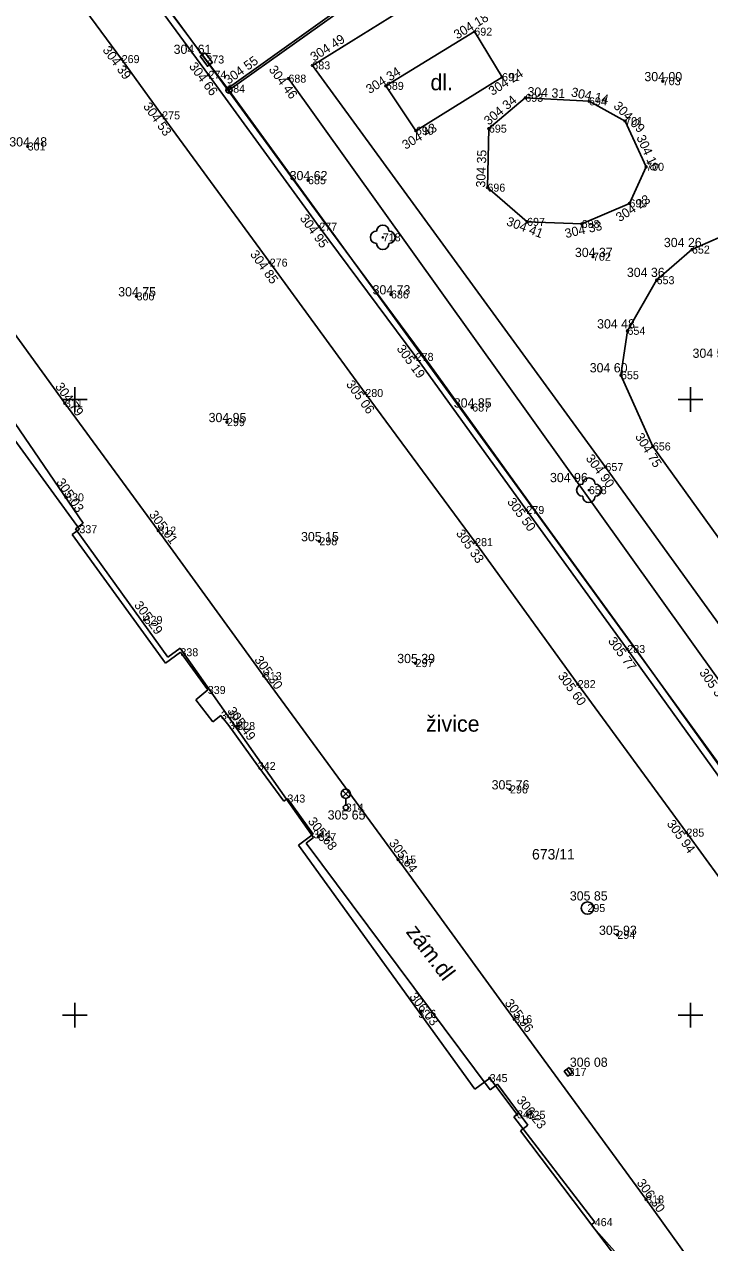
# Model space of a CAD drawing. Extents: x -492811 to -492366, y -1127107 to -1126748.
# Drawn here: x -492641.63 to -492619.38, y -1126927.39 to -1126887.82 of the extents above; entities that cross this region are included whole.
import ezdxf

# ---------------------------------------------------------------- set-up
doc = ezdxf.new("R2010")
doc.units = 0
for name, color, linetype in [('body', 7, 'Continuous'), ('kanalizace', 7, 'Continuous'), ('katastrální mapa', 7, 'Continuous'), ('oplocení', 7, 'Continuous'), ('plyn', 7, 'Continuous'), ('podrobný výškový bod', 7, 'Continuous'), ('popis ploch', 7, 'Continuous'), ('rozhraní ploch', 7, 'Continuous'), ('stavební objekt', 7, 'Continuous'), ('stromy', 7, 'Continuous'), ('síť', 7, 'Continuous'), ('veřejné osvětlení', 7, 'Continuous'), ('vstup na pozemek', 7, 'Continuous'), ('výšky', 7, 'Continuous'), ('čísla bodů', 7, 'Continuous')]:
    doc.layers.add(name, color=color, linetype=linetype)

msp = doc.modelspace()

# ---------------------------------------------------------------- linework, layer by layer
at = {"layer": 'body'}
for p, q in [((-492627.022, -1126888.052), (-492627.022, -1126888.052)), ((-492638.475, -1126888.943), (-492638.475, -1126888.943)), ((-492635.726, -1126888.956), (-492635.726, -1126888.956)), ((-492635.656, -1126889.453), (-492635.656, -1126889.453)), ((-492632.283, -1126889.147), (-492632.283, -1126889.147)), ((-492635.048, -1126889.905), (-492635.048, -1126889.905)), ((-492633.06, -1126889.577), (-492633.06, -1126889.577)), ((-492629.894, -1126889.813), (-492629.894, -1126889.813)), ((-492626.122, -1126889.528), (-492626.122, -1126889.528)), ((-492620.903, -1126889.662), (-492620.903, -1126889.662)), ((-492625.366, -1126890.2), (-492625.366, -1126890.2)), ((-492623.298, -1126890.315), (-492623.298, -1126890.315)), ((-492637.159, -1126890.77), (-492637.159, -1126890.77)), ((-492622.123, -1126890.955), (-492622.123, -1126890.955)), ((-492628.919, -1126891.27), (-492628.919, -1126891.27)), ((-492626.549, -1126891.202), (-492626.549, -1126891.202)), ((-492641.528, -1126891.781), (-492641.528, -1126891.781)), ((-492621.442, -1126892.441), (-492621.442, -1126892.441)), ((-492632.423, -1126892.877), (-492632.423, -1126892.877)), ((-492626.597, -1126893.119), (-492626.597, -1126893.119)), ((-492621.986, -1126893.629), (-492621.986, -1126893.629)), ((-492625.309, -1126894.23), (-492625.309, -1126894.23)), ((-492632.058, -1126894.387), (-492632.058, -1126894.387)), ((-492623.536, -1126894.298), (-492623.536, -1126894.298)), ((-492629.995, -1126894.732), (-492629.995, -1126894.732)), ((-492623.168, -1126895.362), (-492623.168, -1126895.362)), ((-492619.955, -1126895.131), (-492619.955, -1126895.131)), ((-492633.667, -1126895.554), (-492633.667, -1126895.554)), ((-492621.102, -1126896.125), (-492621.102, -1126896.125)), ((-492629.73, -1126896.587), (-492629.73, -1126896.587)), ((-492637.991, -1126896.651), (-492637.991, -1126896.651)), ((-492622.049, -1126897.769), (-492622.049, -1126897.769)), ((-492628.927, -1126898.616), (-492628.927, -1126898.616)), ((-492622.26, -1126899.211), (-492622.26, -1126899.211)), ((-492630.562, -1126899.789), (-492630.562, -1126899.789)), ((-492640.318, -1126900.123), (-492640.318, -1126900.123)), ((-492627.092, -1126900.26), (-492627.092, -1126900.26)), ((-492635.055, -1126900.735), (-492635.055, -1126900.735)), ((-492621.225, -1126901.525), (-492621.225, -1126901.525)), ((-492622.764, -1126902.193), (-492622.764, -1126902.193)), ((-492623.303, -1126902.945), (-492623.303, -1126902.945)), ((-492640.28, -1126903.178), (-492640.28, -1126903.178)), ((-492625.331, -1126903.589), (-492625.331, -1126903.589)), ((-492639.848, -1126904.212), (-492639.848, -1126904.212)), ((-492637.286, -1126904.258), (-492637.286, -1126904.258)), ((-492632.054, -1126904.605), (-492632.054, -1126904.605)), ((-492626.997, -1126904.633), (-492626.997, -1126904.633)), ((-492637.73, -1126907.16), (-492637.73, -1126907.16)), ((-492622.054, -1126908.105), (-492622.054, -1126908.105)), ((-492636.568, -1126908.209), (-492636.568, -1126908.209)), ((-492628.93, -1126908.562), (-492628.93, -1126908.562)), ((-492633.857, -1126908.983), (-492633.857, -1126908.983)), ((-492623.664, -1126909.244), (-492623.664, -1126909.244)), ((-492635.678, -1126909.435), (-492635.678, -1126909.435)), ((-492635.254, -1126910.263), (-492635.254, -1126910.263)), ((-492634.99, -1126910.585), (-492634.99, -1126910.585)), ((-492634.721, -1126910.604), (-492634.721, -1126910.604)), ((-492634.055, -1126911.903), (-492634.055, -1126911.903)), ((-492625.864, -1126912.665), (-492625.864, -1126912.665)), ((-492633.093, -1126912.961), (-492633.093, -1126912.961)), ((-492631.198, -1126913.255), (-492631.198, -1126913.255)), ((-492632.255, -1126914.122), (-492632.255, -1126914.122)), ((-492632.083, -1126914.206), (-492632.083, -1126914.206)), ((-492620.135, -1126914.068), (-492620.135, -1126914.068)), ((-492629.493, -1126914.945), (-492629.493, -1126914.945)), ((-492623.35, -1126916.517), (-492623.35, -1126916.517)), ((-492622.377, -1126917.389), (-492622.377, -1126917.389)), ((-492628.84, -1126919.953), (-492628.84, -1126919.953)), ((-492625.724, -1126920.128), (-492625.724, -1126920.128)), ((-492623.96, -1126921.841), (-492623.96, -1126921.841)), ((-492626.524, -1126922.041), (-492626.524, -1126922.041)), ((-492625.636, -1126923.22), (-492625.636, -1126923.22)), ((-492625.293, -1126923.234), (-492625.293, -1126923.234)), ((-492621.441, -1126925.982), (-492621.441, -1126925.982)), ((-492623.112, -1126926.72), (-492623.112, -1126926.72))]:
    msp.add_line(p, q, dxfattribs=at)
at = {"layer": 'kanalizace'}
msp.add_line((-492624.018, -1126921.76), (-492623.902, -1126921.922), dxfattribs=at)
msp.add_lwpolyline([(-492623.937, -1126921.701), (-492623.82, -1126921.864), (-492623.983, -1126921.981), (-492624.1, -1126921.818)], close=True, dxfattribs=at)
msp.add_circle((-492623.35, -1126916.517), 0.2, dxfattribs=at)
at = {"layer": 'katastrální mapa'}
for p, q in [((-492634.99, -1126889.95), (-492612.83, -1126874.18)), ((-492637.39, -1126886.75), (-492634.99, -1126889.95)), ((-492634.99, -1126889.95), (-492613.17, -1126919.98)), ((-492642.26, -1126900.3), (-492639.72, -1126904.02)), ((-492639.97, -1126904.2), (-492639.72, -1126904.02)), ((-492639.97, -1126904.2), (-492636.98, -1126908.37)), ((-492636.98, -1126908.37), (-492636.57, -1126908.08)), ((-492636.57, -1126908.08), (-492632.24, -1126914.23)), ((-492632.48, -1126914.41), (-492632.24, -1126914.23)), ((-492632.48, -1126914.41), (-492626.51, -1126922.42)), ((-492626.51, -1126922.42), (-492626.27, -1126922.24)), ((-492626.27, -1126922.24), (-492625.28, -1126923.57)), ((-492625.52, -1126923.75), (-492625.28, -1126923.57)), ((-492625.52, -1126923.75), (-492622.44, -1126927.84))]:
    msp.add_line(p, q, dxfattribs=at)
for radius in [0.1, 0.002]:
    msp.add_circle((-492634.99, -1126889.95), radius, dxfattribs=at)
at = {"layer": 'oplocení'}
for p, q in [((-492626.413, -1126883.743), (-492635.052, -1126889.908)), ((-492638.534, -1126885.53), (-492635.656, -1126889.453)), ((-492638.357, -1126885.4), (-492635.478, -1126889.323)), ((-492635.656, -1126889.453), (-492632.058, -1126894.387)), ((-492635.478, -1126889.323), (-492631.881, -1126894.257)), ((-492633.06, -1126889.577), (-492619.066, -1126909.124)), ((-492631.881, -1126894.257), (-492628.749, -1126898.486)), ((-492632.058, -1126894.387), (-492628.927, -1126898.616)), ((-492628.927, -1126898.616), (-492625.331, -1126903.589)), ((-492628.749, -1126898.486), (-492625.153, -1126903.46)), ((-492625.331, -1126903.589), (-492622.054, -1126908.105)), ((-492625.153, -1126903.46), (-492621.876, -1126907.976)), ((-492622.054, -1126908.105), (-492618.674, -1126912.816)), ((-492621.876, -1126907.976), (-492618.496, -1126912.687))]:
    msp.add_line(p, q, dxfattribs=at)
at = {"layer": 'plyn'}
msp.add_lwpolyline([(-492635.762, -1126888.735), (-492635.528, -1126889.059), (-492635.69, -1126889.177), (-492635.924, -1126888.853)], close=True, dxfattribs=at)
at = {"layer": 'podrobný výškový bod'}
for centre in [(-492627.022, -1126888.052), (-492638.475, -1126888.943), (-492632.283, -1126889.147), (-492635.656, -1126889.453), (-492626.122, -1126889.528), (-492635.048, -1126889.905), (-492633.06, -1126889.577), (-492629.894, -1126889.813), (-492620.903, -1126889.662), (-492625.366, -1126890.2), (-492623.298, -1126890.315), (-492637.159, -1126890.77), (-492622.123, -1126890.955), (-492628.919, -1126891.27), (-492626.549, -1126891.202), (-492641.528, -1126891.781), (-492621.442, -1126892.441), (-492632.423, -1126892.877), (-492626.597, -1126893.119), (-492621.986, -1126893.629), (-492625.309, -1126894.23), (-492632.058, -1126894.387), (-492623.536, -1126894.298), (-492623.168, -1126895.362), (-492619.955, -1126895.131), (-492633.667, -1126895.554), (-492621.102, -1126896.125), (-492637.991, -1126896.651), (-492629.73, -1126896.587), (-492622.049, -1126897.769), (-492628.927, -1126898.616), (-492622.26, -1126899.211), (-492630.562, -1126899.789), (-492640.318, -1126900.123), (-492627.092, -1126900.26), (-492635.055, -1126900.735), (-492621.225, -1126901.525), (-492622.764, -1126902.193), (-492640.28, -1126903.178), (-492625.331, -1126903.589), (-492637.286, -1126904.258), (-492632.054, -1126904.605), (-492626.997, -1126904.633), (-492637.73, -1126907.16), (-492622.054, -1126908.105), (-492628.93, -1126908.562), (-492633.857, -1126908.983), (-492623.664, -1126909.244), (-492634.721, -1126910.604), (-492625.864, -1126912.665), (-492620.135, -1126914.068), (-492632.083, -1126914.206), (-492629.493, -1126914.945), (-492622.377, -1126917.389), (-492628.775, -1126919.904), (-492625.724, -1126920.128), (-492626.524, -1126922.041), (-492625.636, -1126923.22), (-492625.293, -1126923.234), (-492621.441, -1126925.982)]:
    msp.add_circle(centre, 0.03, dxfattribs=at)
at = {"layer": 'rozhraní ploch'}
for p, q in [((-492641.178, -1126885.289), (-492638.475, -1126888.943)), ((-492632.283, -1126889.147), (-492628.819, -1126886.997)), ((-492627.022, -1126888.052), (-492629.894, -1126889.813)), ((-492626.122, -1126889.528), (-492627.022, -1126888.052)), ((-492638.475, -1126888.943), (-492637.159, -1126890.77)), ((-492622.764, -1126902.193), (-492632.283, -1126889.147)), ((-492629.894, -1126889.813), (-492628.919, -1126891.27)), ((-492628.919, -1126891.27), (-492626.122, -1126889.528)), ((-492625.366, -1126890.2), (-492626.549, -1126891.202)), ((-492623.298, -1126890.315), (-492625.366, -1126890.2)), ((-492622.123, -1126890.955), (-492623.298, -1126890.315)), ((-492637.159, -1126890.77), (-492633.667, -1126895.554)), ((-492621.442, -1126892.441), (-492622.123, -1126890.955)), ((-492626.549, -1126891.202), (-492626.597, -1126893.119)), ((-492621.986, -1126893.629), (-492621.442, -1126892.441)), ((-492626.597, -1126893.119), (-492625.309, -1126894.23)), ((-492623.536, -1126894.298), (-492621.986, -1126893.629)), ((-492625.309, -1126894.23), (-492623.536, -1126894.298)), ((-492618.056, -1126894.29), (-492619.955, -1126895.131)), ((-492640.318, -1126900.123), (-492644.056, -1126894.975)), ((-492619.955, -1126895.131), (-492621.102, -1126896.125)), ((-492633.667, -1126895.554), (-492630.562, -1126899.789)), ((-492621.102, -1126896.125), (-492622.049, -1126897.769)), ((-492622.049, -1126897.769), (-492622.26, -1126899.211)), ((-492622.26, -1126899.211), (-492621.225, -1126901.525)), ((-492630.562, -1126899.789), (-492626.997, -1126904.633)), ((-492637.286, -1126904.258), (-492640.318, -1126900.123)), ((-492621.225, -1126901.525), (-492616.962, -1126907.457)), ((-492618.217, -1126908.496), (-492622.764, -1126902.193)), ((-492633.857, -1126908.983), (-492637.286, -1126904.258)), ((-492626.997, -1126904.633), (-492623.664, -1126909.244)), ((-492629.493, -1126914.945), (-492633.857, -1126908.983)), ((-492623.664, -1126909.244), (-492620.135, -1126914.068)), ((-492620.135, -1126914.068), (-492617.173, -1126918.142)), ((-492625.724, -1126920.128), (-492629.493, -1126914.945)), ((-492621.441, -1126925.982), (-492625.724, -1126920.128)), ((-492618.532, -1126930.024), (-492621.441, -1126925.982))]:
    msp.add_line(p, q, dxfattribs=at)
at = {"layer": 'stavební objekt'}
for p, q in [((-492639.848, -1126904.212), (-492642.526, -1126900.527)), ((-492639.848, -1126904.212), (-492642.526, -1126900.527)), ((-492640.086, -1126904.382), (-492639.848, -1126904.212)), ((-492637.052, -1126908.561), (-492640.086, -1126904.382)), ((-492636.568, -1126908.209), (-492637.052, -1126908.561)), ((-492635.678, -1126909.435), (-492636.568, -1126908.209)), ((-492635.678, -1126909.435), (-492636.067, -1126909.752)), ((-492635.514, -1126910.467), (-492636.067, -1126909.752)), ((-492635.254, -1126910.263), (-492635.514, -1126910.467)), ((-492635.254, -1126910.263), (-492634.99, -1126910.585)), ((-492633.208, -1126913.044), (-492634.055, -1126911.903)), ((-492633.093, -1126912.961), (-492633.208, -1126913.044)), ((-492632.255, -1126914.122), (-492633.093, -1126912.961)), ((-492632.255, -1126914.122), (-492632.73, -1126914.48)), ((-492627.001, -1126922.4), (-492632.73, -1126914.48)), ((-492626.524, -1126922.041), (-492627.001, -1126922.4)), ((-492625.636, -1126923.22), (-492626.524, -1126922.041)), ((-492625.636, -1126923.22), (-492625.744, -1126923.298)), ((-492623.112, -1126926.72), (-492625.744, -1126923.298)), ((-492623.112, -1126926.72), (-492623.228, -1126926.807)), ((-492623.228, -1126926.807), (-492622.308, -1126927.85))]:
    msp.add_line(p, q, dxfattribs=at)
at = {"layer": 'stromy'}
for centre in [(-492629.995, -1126894.732), (-492623.303, -1126902.945)]:
    msp.add_circle(centre, 0.02, dxfattribs=at)
for centre, start, end in [((-492630.195, -1126894.732), 90, 270), ((-492629.995, -1126894.532), 360, 180), ((-492629.795, -1126894.732), 270, 90), ((-492629.995, -1126894.932), 180, 0), ((-492623.303, -1126902.745), 360, 180), ((-492623.503, -1126902.945), 90, 270), ((-492623.103, -1126902.945), 270, 90), ((-492623.303, -1126903.145), 180, 0)]:
    msp.add_arc(centre, 0.2, start, end, dxfattribs=at)
at = {"layer": 'síť'}
for p, q in [((-492640, -1126899.6), (-492640, -1126900.4)), ((-492620, -1126899.6), (-492620, -1126900.4)), ((-492640.4, -1126900), (-492639.6, -1126900)), ((-492620.4, -1126900), (-492619.6, -1126900)), ((-492640, -1126919.6), (-492640, -1126920.4)), ((-492620, -1126919.6), (-492620, -1126920.4)), ((-492640.4, -1126920), (-492639.6, -1126920)), ((-492620.4, -1126920), (-492619.6, -1126920))]:
    msp.add_line(p, q, dxfattribs=at)
at = {"layer": 'veřejné osvětlení'}
for p, q in [((-492631.304, -1126912.911), (-492631.092, -1126912.699)), ((-492631.304, -1126912.699), (-492631.092, -1126912.911)), ((-492631.198, -1126912.955), (-492631.198, -1126913.175))]:
    msp.add_line(p, q, dxfattribs=at)
for centre, radius in [((-492631.198, -1126912.805), 0.15), ((-492631.198, -1126913.255), 0.08)]:
    msp.add_circle(centre, radius, dxfattribs=at)
at = {"layer": 'vstup na pozemek'}
msp.add_line((-492634.055, -1126911.903), (-492634.99, -1126910.585), dxfattribs=at)

# ---------------------------------------------------------------- texts
at = {"layer": 'katastrální mapa'}
msp.add_text('673/11', height=0.34, dxfattribs=at).set_placement((-492625.149, -1126914.941))
at = {"layer": 'popis ploch'}
for s, p in [('dl.', (-492628.447, -1126889.956)), ('živice', (-492628.591, -1126910.789))]:
    msp.add_text(s, height=0.52, dxfattribs=at).set_placement(p)
msp.add_text('zám.dl', height=0.52, rotation=307.4503, dxfattribs=at).set_placement((-492629.265, -1126917.297))
at = {"layer": 'výšky'}
for s, rotation, p in [('304 18 ', 31.3444, (-492627.578, -1126888.309)), ('304 49 ', 32.5039, (-492632.229, -1126889.03)), ('304 39 ', 306.4769, (-492639.111, -1126888.653)), ('304 66 ', 306.6812, (-492636.303, -1126889.181)), ('304 55 ', 35.6918, (-492635.008, -1126889.778)), ('304 46 ', 306.5156, (-492633.714, -1126889.286)), ('304 34 ', 32.0188, (-492630.424, -1126890.082)), ('304 24 ', 32.505, (-492626.439, -1126890.143)), ('304 31 ', 356.9496, (-492625.304, -1126890.147)), ('304 14 ', 347.8519, (-492623.899, -1126890.149)), ('304 34 ', 39.8888, (-492626.557, -1126891.11)), ('304 53 ', 305.7181, (-492637.792, -1126890.48)), ('304 09 ', 314.4722, (-492622.525, -1126890.492)), ('304 43 ', 31.2092, (-492629.255, -1126891.892)), ('304 16 ', 294.42, (-492621.766, -1126891.486)), ('304 35 ', 87.9608, (-492626.67, -1126893.119)), ('304 23 ', 33.1954, (-492622.302, -1126894.244)), ('304 95 ', 305.8559, (-492632.704, -1126894.116)), ('304 41 ', 339.3163, (-492626.006, -1126894.33)), ('304 33 ', 12.8169, (-492624.046, -1126894.759)), ('304 85 ', 305.5135, (-492634.321, -1126895.281)), ('305 19 ', 306.0761, (-492629.56, -1126898.353)), ('305 06 ', 306.0241, (-492631.203, -1126899.507)), ('304 79 ', 305.9241, (-492640.649, -1126899.581)), ('304 75 ', 301.717, (-492621.814, -1126901.201)), ('304 90 ', 306.5511, (-492623.42, -1126901.916)), ('305 03 ', 304.0022, (-492640.613, -1126902.684)), ('305 50 ', 306.3074, (-492625.972, -1126903.327)), ('305 01 ', 306.4446, (-492637.601, -1126903.739)), ('305 33 ', 305.0959, (-492627.633, -1126904.348)), ('305 29 ', 306.5518, (-492638.085, -1126906.681)), ('305 77 ', 305.707, (-492622.695, -1126907.846)), ('305 30 ', 305.7417, (-492634.181, -1126908.455)), ('305 60 ', 305.6634, (-492624.325, -1126908.982)), ('305 37 ', 305.3328, (-492619.731, -1126908.871)), ('305 49 ', 305.9495, (-492635.06, -1126910.116)), ('305 68 ', 307.9394, (-492632.445, -1126913.708)), ('305 94 ', 306.1871, (-492620.789, -1126913.782)), ('305 64 ', 306.2746, (-492629.81, -1126914.411)), ('306 03 ', 308.0104, (-492629.149, -1126919.405)), ('305 96 ', 306.4486, (-492626.048, -1126919.606)), ('306 23 ', 308.9441, (-492625.668, -1126922.77)), ('306 30 ', 305.8672, (-492621.764, -1126925.446))]:
    msp.add_text(s, height=0.3, rotation=rotation, dxfattribs=at).set_placement(p)
for s, p in [('304 61 ', (-492636.787, -1126888.774)), ('304 00 ', (-492621.499, -1126889.662)), ('304 48 ', (-492642.124, -1126891.781)), ('304 62 ', (-492633.019, -1126892.877)), ('304 26 ', (-492620.866, -1126895.05)), ('304 37 ', (-492623.755, -1126895.373)), ('304 36 ', (-492622.067, -1126896.021)), ('304 75 ', (-492638.587, -1126896.651)), ('304 73 ', (-492630.326, -1126896.587)), ('304 48 ', (-492623.035, -1126897.693)), ('304 52 ', (-492619.935, -1126898.646)), ('304 60 ', (-492623.274, -1126899.119)), ('304 85 ', (-492627.688, -1126900.26)), ('304 95 ', (-492635.651, -1126900.735)), ('304 96 ', (-492624.565, -1126902.685)), ('305 15 ', (-492632.65, -1126904.605)), ('305 39 ', (-492629.526, -1126908.562)), ('305 76 ', (-492626.46, -1126912.665)), ('305 65 ', (-492631.785, -1126913.643)), ('305 85 ', (-492623.92, -1126916.273)), ('305 93 ', (-492622.973, -1126917.389)), ('306 08 ', (-492623.92, -1126921.675))]:
    msp.add_text(s, height=0.3, dxfattribs=at).set_placement(p)
at = {"layer": 'čísla bodů'}
for s, p in [('692', (-492627.022, -1126888.182)), ('269', (-492638.475, -1126889.073)), ('273', (-492635.726, -1126889.086)), ('683', (-492632.283, -1126889.277)), ('274', (-492635.656, -1126889.583)), ('688', (-492633.06, -1126889.707)), ('691', (-492626.122, -1126889.658)), ('684', (-492635.048, -1126890.035)), ('689', (-492629.894, -1126889.943)), ('703', (-492620.903, -1126889.792)), ('693', (-492625.366, -1126890.33)), ('694', (-492623.298, -1126890.445)), ('275', (-492637.159, -1126890.9)), ('695', (-492626.549, -1126891.332)), ('701', (-492622.123, -1126891.085)), ('690', (-492628.919, -1126891.4)), ('301', (-492641.528, -1126891.911)), ('700', (-492621.442, -1126892.571)), ('685', (-492632.423, -1126893.007)), ('696', (-492626.597, -1126893.249)), ('699', (-492621.986, -1126893.759)), ('277', (-492632.058, -1126894.517)), ('697', (-492625.309, -1126894.36)), ('698', (-492623.536, -1126894.428)), ('718', (-492629.995, -1126894.862)), ('652', (-492619.955, -1126895.261)), ('276', (-492633.667, -1126895.684)), ('702', (-492623.168, -1126895.492)), ('653', (-492621.102, -1126896.255)), ('300', (-492637.991, -1126896.781)), ('686', (-492629.73, -1126896.717)), ('654', (-492622.049, -1126897.899)), ('278', (-492628.927, -1126898.746)), ('655', (-492622.26, -1126899.341)), ('280', (-492630.562, -1126899.919)), ('311', (-492640.318, -1126900.253)), ('687', (-492627.092, -1126900.39)), ('299', (-492635.055, -1126900.865)), ('656', (-492621.225, -1126901.655)), ('657', (-492622.764, -1126902.323)), ('658', (-492623.303, -1126903.075)), ('330', (-492640.28, -1126903.308)), ('279', (-492625.331, -1126903.719)), ('337', (-492639.848, -1126904.342)), ('312', (-492637.286, -1126904.388)), ('298', (-492632.054, -1126904.735)), ('281', (-492626.997, -1126904.763)), ('329', (-492637.73, -1126907.29)), ('338', (-492636.568, -1126908.339)), ('283', (-492622.054, -1126908.235)), ('297', (-492628.93, -1126908.692)), ('313', (-492633.857, -1126909.113)), ('339', (-492635.678, -1126909.565)), ('282', (-492623.664, -1126909.374)), ('340', (-492635.254, -1126910.393)), ('341', (-492634.99, -1126910.715)), ('328', (-492634.721, -1126910.734)), ('342', (-492634.055, -1126912.033)), ('343', (-492633.093, -1126913.091)), ('296', (-492625.864, -1126912.795)), ('314', (-492631.198, -1126913.385)), ('344', (-492632.255, -1126914.252)), ('285', (-492620.135, -1126914.198)), ('327', (-492632.083, -1126914.336)), ('315', (-492629.493, -1126915.075)), ('295', (-492623.35, -1126916.647)), ('294', (-492622.377, -1126917.519)), ('326', (-492628.84, -1126920.083)), ('316', (-492625.724, -1126920.258)), ('345', (-492626.524, -1126922.171)), ('317', (-492623.96, -1126921.971)), ('346', (-492625.636, -1126923.35)), ('325', (-492625.293, -1126923.364)), ('318', (-492621.441, -1126926.112)), ('464', (-492623.112, -1126926.85))]:
    msp.add_text(s, height=0.26, dxfattribs=at).set_placement(p)

doc.saveas('drawing.dxf')
